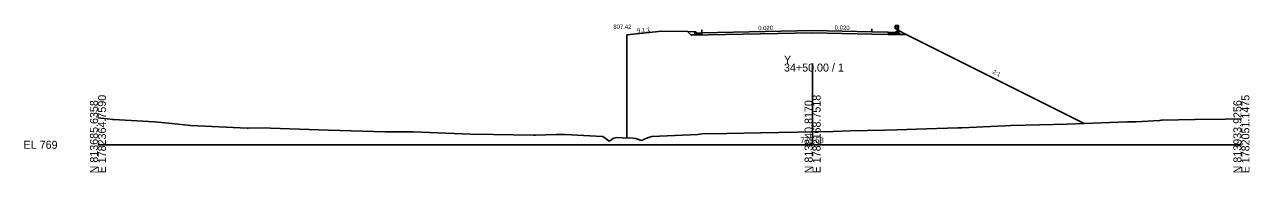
# Model space of a CAD drawing. Extents: x -12583 to 5303, y -44 to 25667.
# Drawn here: x 1874.3 to 2302.8, y 4990.3 to 5042.1 of the extents above; entities that cross this region are included whole.
import ezdxf

# ---------------------------------------------------------------- set-up
doc = ezdxf.new("R2010")
doc.units = 0
for name, color, linetype in [('Exist Cross Section Cell', 7, 'Continuous'), ('Exist XS Center Line Elevation Label', 7, 'Continuous'), ('Exist XS Ground Line', 7, 'Continuous'), ('Prop XS Ditch Standard Text', 7, 'Continuous'), ('Prop XS Dump Level', 7, 'Continuous'), ('Prop XS Earthwork Shape', 7, 'Continuous'), ('Prop XS EOT Tick Mark', 7, 'Continuous'), ('Prop XS Finish Grade', 7, 'Continuous'), ('Prop XS Finish Grade CurbGutter', 7, 'Continuous'), ('Prop XS Finish Grade Earthwork', 7, 'Continuous'), ('Prop XS Finish Grade Paved Shoulder', 7, 'Continuous'), ('Prop XS Finish Grade Pavement', 7, 'Continuous'), ('Prop XS Guardrail', 7, 'Continuous'), ('Prop XS Pvmt Edge Slope', 7, 'Continuous'), ('Prop XS SE Text', 7, 'Continuous'), ('Prop XS Side Slope Text', 7, 'Continuous'), ('Prop XS Subgrade CurbGutter', 7, 'Continuous'), ('Prop XS Subgrade Earthwork', 7, 'Continuous')]:
    doc.layers.add(name, color=color, linetype=linetype)

msp = doc.modelspace()

# ---------------------------------------------------------------- linework, layer by layer
at = {"layer": 'Exist Cross Section Cell'}
for p, q in [((2150, 5000), (2150, 5028.4)), ((1900, 5000), (2150, 5000)), ((2150, 5000), (2300, 5000))]:
    msp.add_line(p, q, dxfattribs=at)
at = {"layer": 'Exist XS Ground Line'}
for p, q in [((1900, 5009.47), (1904.31, 5008.98)), ((1904.31, 5008.98), (1905.12, 5008.89)), ((1905.12, 5008.89), (1905.42, 5008.87)), ((1905.42, 5008.87), (1919.78, 5008.07)), ((1919.78, 5008.07), (1925.88, 5007.42)), ((1925.88, 5007.42), (1932.5, 5006.75)), ((1932.5, 5006.75), (1952.17, 5005.81)), ((1952.17, 5005.81), (1952.56, 5005.81)), ((1952.56, 5005.81), (1958.73, 5005.87)), ((1958.73, 5005.87), (1960.34, 5005.81)), ((1960.34, 5005.81), (1980.68, 5005.07)), ((2175.2, 5005.06), (2179.43, 5005.27)), ((2179.43, 5005.27), (2189.87, 5005.58)), ((2189.87, 5005.58), (2200.75, 5005.96)), ((2200.75, 5005.96), (2202.18, 5005.98)), ((2202.18, 5005.98), (2217.24, 5006.59)), ((2217.24, 5006.59), (2219.3, 5006.72)), ((2219.3, 5006.72), (2229.36, 5007.01)), ((2229.36, 5007.01), (2239.05, 5007.24)), ((2239.05, 5007.24), (2250.94, 5007.66)), ((2250.94, 5007.66), (2260.18, 5008.01)), ((2260.18, 5008.01), (2263.08, 5008.07)), ((2263.08, 5008.07), (2271.38, 5008.53)), ((2271.38, 5008.53), (2271.77, 5008.55)), ((2271.77, 5008.55), (2272.26, 5008.57)), ((2272.26, 5008.57), (2283.7, 5008.79)), ((2283.7, 5008.79), (2294.41, 5008.97)), ((2294.41, 5008.97), (2300, 5009.07)), ((1980.68, 5005.07), (1984.56, 5004.96)), ((1984.56, 5004.96), (2000.47, 5004.53)), ((2000.47, 5004.53), (2010.32, 5004.49)), ((2010.32, 5004.49), (2030.32, 5003.74)), ((2030.32, 5003.74), (2038.38, 5003.64)), ((2038.38, 5003.64), (2052.39, 5003.39)), ((2052.39, 5003.39), (2053.06, 5003.4)), ((2053.06, 5003.4), (2060.3, 5003.57)), ((2060.3, 5003.57), (2063.55, 5003.54)), ((2063.55, 5003.54), (2069.82, 5003.23)), ((2069.82, 5003.23), (2076.46, 5002.87)), ((2076.46, 5002.87), (2076.92, 5002.63)), ((2076.92, 5002.63), (2078.81, 5001.24)), ((2078.81, 5001.24), (2080.5, 5002.27)), ((2080.5, 5002.27), (2081.62, 5002.55)), ((2081.62, 5002.55), (2083.54, 5002.48)), ((2083.54, 5002.48), (2087.19, 5002.36)), ((2087.19, 5002.36), (2088.05, 5002.21)), ((2088.05, 5002.21), (2090.18, 5001.55)), ((2090.18, 5001.55), (2092.21, 5002.42)), ((2092.21, 5002.42), (2093.78, 5002.86)), ((2093.78, 5002.86), (2109.91, 5003.63)), ((2109.91, 5003.63), (2111.31, 5003.84)), ((2111.31, 5003.84), (2120.04, 5004)), ((2120.04, 5004), (2131.73, 5004.13)), ((2131.73, 5004.13), (2144.67, 5004.43)), ((2144.67, 5004.43), (2150, 5004.58)), ((2150, 5004.58), (2157.05, 5004.7)), ((2157.05, 5004.7), (2163.29, 5004.83)), ((2163.29, 5004.83), (2175.2, 5005.06))]:
    msp.add_line(p, q, dxfattribs=at)
at = {"layer": 'Prop XS Dump Level'}
for p, q in [((2111.28, 5039.15), (2150, 5039.92)), ((2150, 5039.92), (2170.75, 5039.51))]:
    msp.add_line(p, q, dxfattribs=at)
at = {"layer": 'Prop XS Earthwork Shape'}
msp.add_lwpolyline([(2175.2, 5005.06), (2179.43, 5005.27), (2189.87, 5005.58), (2200.75, 5005.96), (2202.18, 5005.98), (2217.24, 5006.59), (2219.3, 5006.72), (2229.36, 5007.01), (2239.05, 5007.24), (2244.98, 5007.45), (2182.68, 5038.6), (2180.81, 5038.6), (2176.42, 5038.6), (2170.73, 5038.72), (2150, 5039.13), (2107.57, 5038.28), (2106.27, 5039.58), (2097.28, 5039.77), (2085.03, 5038.42), (2085.03, 5002.43), (2087.19, 5002.36), (2088.05, 5002.21), (2090.18, 5001.55), (2092.21, 5002.42), (2093.78, 5002.86), (2109.91, 5003.63), (2111.31, 5003.84), (2120.04, 5004), (2131.73, 5004.13), (2144.67, 5004.43), (2150, 5004.58), (2157.05, 5004.7), (2163.29, 5004.83)], close=True, dxfattribs=at)
at = {"layer": 'Prop XS EOT Tick Mark'}
for p, q in [((2111.28, 5039.15), (2111.28, 5040.15)), ((2170.75, 5039.51), (2170.75, 5040.51))]:
    msp.add_line(p, q, dxfattribs=at)
at = {"layer": 'Prop XS Finish Grade'}
for p, q in [((2108.78, 5039.53), (2106.27, 5039.58)), ((2179.44, 5039.64), (2180.02, 5039.93)), ((2182.68, 5038.6), (2180.02, 5039.93))]:
    msp.add_line(p, q, dxfattribs=at)
at = {"layer": 'Prop XS Finish Grade CurbGutter'}
for p, q in [((2178.75, 5039.3), (2179.44, 5039.64)), ((2108.78, 5039.53), (2109.03, 5039.53)), ((2109.03, 5039.53), (2109.16, 5039.5)), ((2109.25, 5039.41), (2109.16, 5039.5)), ((2109.32, 5039.16), (2109.25, 5039.41)), ((2109.41, 5039.07), (2109.32, 5039.16)), ((2109.53, 5039.04), (2109.41, 5039.07)), ((2111.28, 5039.15), (2109.53, 5039.04)), ((2176.42, 5039.4), (2178.75, 5039.3))]:
    msp.add_line(p, q, dxfattribs=at)
at = {"layer": 'Prop XS Finish Grade Earthwork'}
for p, q in [((2097.28, 5039.77), (2085.03, 5038.42)), ((2106.27, 5039.58), (2097.28, 5039.77)), ((2085.03, 5038.42), (2085.03, 5002.43)), ((2182.68, 5038.6), (2244.98, 5007.45))]:
    msp.add_line(p, q, dxfattribs=at)
at = {"layer": 'Prop XS Finish Grade Paved Shoulder'}
msp.add_line((2170.75, 5039.51), (2176.42, 5039.4), dxfattribs=at)
at = {"layer": 'Prop XS Finish Grade Pavement'}
for p, q in [((2111.28, 5039.15), (2150, 5039.92)), ((2150, 5039.92), (2170.75, 5039.51))]:
    msp.add_line(p, q, dxfattribs=at)
at = {"layer": 'Prop XS Guardrail'}
for p, q in [((2178.78, 5041.5), (2178.75, 5041.44)), ((2178.75, 5041.44), (2178.78, 5041.38)), ((2178.78, 5040.88), (2178.75, 5040.82)), ((2178.75, 5040.82), (2178.78, 5040.76)), ((2179.07, 5041.7), (2178.78, 5041.5)), ((2178.78, 5041.38), (2179.07, 5041.18)), ((2179.07, 5041.08), (2178.78, 5040.88)), ((2178.78, 5040.76), (2179.07, 5040.56)), ((2179.57, 5041.7), (2179.07, 5041.7)), ((2179.07, 5041.18), (2179.07, 5041.08)), ((2179.07, 5040.56), (2179.57, 5040.56)), ((2180.07, 5041.7), (2179.57, 5041.7)), ((2179.57, 5041.7), (2179.57, 5039.2)), ((2180.07, 5039.2), (2180.07, 5041.7))]:
    msp.add_line(p, q, dxfattribs=at)
at = {"layer": 'Prop XS Pvmt Edge Slope'}
for p, q in [((2107.78, 5038.5), (2107.57, 5038.28)), ((2108.78, 5038.52), (2107.78, 5038.5)), ((2179.44, 5038.98), (2180.44, 5038.98)), ((2180.44, 5038.98), (2180.81, 5038.6))]:
    msp.add_line(p, q, dxfattribs=at)
at = {"layer": 'Prop XS Subgrade CurbGutter'}
for p, q in [((2179.44, 5038.98), (2179.44, 5039.64)), ((2108.78, 5038.52), (2108.78, 5039.53)), ((2111.28, 5038.57), (2108.78, 5038.52)), ((2111.28, 5039.15), (2111.28, 5038.57)), ((2176.42, 5039.4), (2176.42, 5038.98)), ((2176.42, 5038.98), (2179.44, 5038.98))]:
    msp.add_line(p, q, dxfattribs=at)
at = {"layer": 'Prop XS Subgrade Earthwork'}
for p, q in [((2107.57, 5038.28), (2106.27, 5039.58)), ((2107.57, 5038.28), (2150, 5039.13)), ((2150, 5039.13), (2170.73, 5038.72)), ((2170.73, 5038.72), (2176.42, 5038.6)), ((2176.42, 5038.6), (2180.81, 5038.6)), ((2180.81, 5038.6), (2182.68, 5038.6))]:
    msp.add_line(p, q, dxfattribs=at)

# ---------------------------------------------------------------- texts
at = {"layer": 'Exist Cross Section Cell'}
for s, p in [('Y', (2140, 5028.4)), ('34+50.00 / 1', (2140, 5025.6)), ('EL 769', (1874, 4998.6))]:
    msp.add_text(s, height=2.8, dxfattribs=at).set_placement(p)
for s, p in [('N 813685.6358', (1900, 4990)), ('E 1782364.7590', (1902.8, 4990)), ('N 813840.8170', (2150, 4990)), ('E 1782168.7518', (2152.8, 4990)), ('N 813933.9256', (2300, 4990)), ('E 1782051.1475', (2302.8, 4990))]:
    msp.add_text(s, height=2.8, rotation=90, dxfattribs=at).set_placement(p)
at = {"layer": 'Exist XS Center Line Elevation Label'}
msp.add_text('773.58', height=2, dxfattribs=at).set_placement((2145.73, 5000.58))
at = {"layer": 'Prop XS Ditch Standard Text'}
msp.add_text('807.42', height=1.5, dxfattribs=at).set_placement((2080.3, 5040.54))
msp.add_text('807.42', height=1.5, dxfattribs=at).set_placement((2080.3, 5040.54))
at = {"layer": 'Prop XS SE Text'}
for rotation, p in [(1.1458, (2131, 5040.04)), (358.8542, (2157.75, 5040.27))]:
    msp.add_text('0.020', height=1.5, rotation=rotation, dxfattribs=at).set_placement(p)
at = {"layer": 'Prop XS Side Slope Text'}
for s, rotation, p in [('9.1:1', 5.6972, (2088.66, 5039.16)), ('2:1', 333.4349, (2212.77, 5025.04))]:
    msp.add_text(s, height=1.5, rotation=rotation, dxfattribs=at).set_placement(p)

doc.saveas('drawing.dxf')
